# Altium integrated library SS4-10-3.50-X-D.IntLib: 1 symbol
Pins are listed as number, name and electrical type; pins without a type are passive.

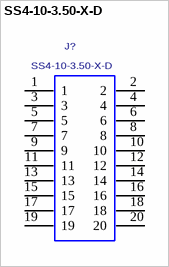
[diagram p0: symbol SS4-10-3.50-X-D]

## SS4-10-3.50-X-D
designator J?
0.4MM SOCKET STRIP ASSEMBLY, 20 PINS.; MANUFACTURER: SAMTEC
footprint SS4-10-3.50-X-D
pins: 1, 2, 3, 4, 5, 6, 7, 8, 9, 10, 11, 12, 13, 14, 15, 16, 17, 18, 19, 20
